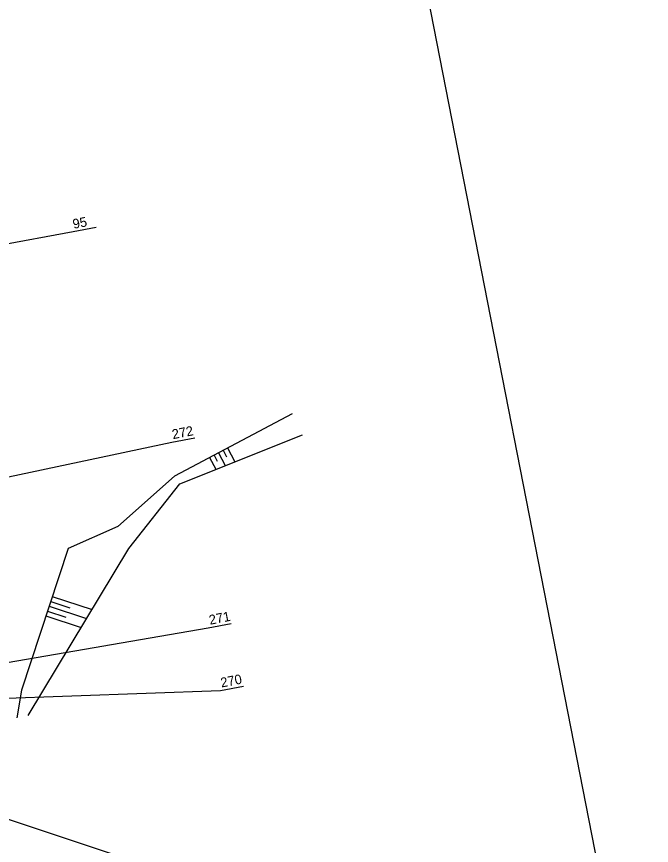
# Model space of a CAD drawing. Extents: x -545967 to -545044, y -1122650 to -1118491.
# Drawn here: x -545637.8 to -545513.8, y -1119258 to -1119096.1 of the extents above; entities that cross this region are included whole.
import ezdxf

# ---------------------------------------------------------------- set-up
doc = ezdxf.new("R2010")
doc.units = 0
for name, color, linetype in [('so180602', 7, 'Continuous'), ('Vrstva 10', 7, 'Continuous'), ('Vrstva 62', 7, 'Continuous'), ('Vrstva 63', 7, 'Continuous')]:
    doc.layers.add(name, color=color, linetype=linetype)

msp = doc.modelspace()

# ---------------------------------------------------------------- linework, layer by layer
at = {"layer": 'Vrstva 10'}
msp.add_line((-545675.17, -1118491.08), (-545513.83, -1119315.44), dxfattribs=at)
at = {"layer": 'Vrstva 62'}
for points in [[(-545584, -1119173.66), (-545606.97, -1119185.84)], [(-545615.87, -1119200), (-545605.93, -1119187.32), (-545581.98, -1119177.75)], [(-545598.35, -1119181.27), (-545597.03, -1119183.77)], [(-545597.47, -1119180.8), (-545596.78, -1119182.1)], [(-545596.59, -1119180.33), (-545595.16, -1119183.02)], [(-545600.12, -1119182.21), (-545598.9, -1119184.51)], [(-545599.24, -1119181.74), (-545598.6, -1119182.94)], [(-545606.97, -1119185.84), (-545618, -1119195.68), (-545627.74, -1119200)], [(-545627.74, -1119200), (-545636.83, -1119227.67), (-545637.76, -1119233.04)], [(-545635.55, -1119232.61), (-545615.87, -1119200)], [(-545631.13, -1119210.31), (-545627.36, -1119211.55)], [(-545630.82, -1119209.36), (-545623.06, -1119211.91)], [(-545631.75, -1119212.21), (-545628.2, -1119213.38)], [(-545631.44, -1119211.26), (-545624.12, -1119213.67)], [(-545632.07, -1119213.16), (-545625.18, -1119215.42)]]:
    msp.add_lwpolyline(points, dxfattribs=at)
at = {"layer": 'Vrstva 63'}
for p, q in [((-545622.26, -1119137.25), (-545626.71, -1119138.12)), ((-545626.71, -1119138.12), (-545690.95, -1119149.85)), ((-545607.45, -1119179.27), (-545702.19, -1119199.37)), ((-545603.01, -1119178.4), (-545607.45, -1119179.27)), ((-545603.01, -1119178.4), (-545607.45, -1119179.27)), ((-545603.01, -1119178.4), (-545607.45, -1119179.27)), ((-545600.35, -1119215.54), (-545663.35, -1119226.44)), ((-545595.91, -1119214.67), (-545600.35, -1119215.54)), ((-545595.91, -1119214.67), (-545600.35, -1119215.54)), ((-545595.91, -1119214.67), (-545600.35, -1119215.54)), ((-545597.96, -1119227.77), (-545677.04, -1119230.65)), ((-545593.51, -1119226.91), (-545597.96, -1119227.77)), ((-545593.51, -1119226.91), (-545597.96, -1119227.77)), ((-545593.51, -1119226.91), (-545597.96, -1119227.77)), ((-545589.82, -1119269.35), (-545695.29, -1119234.41))]:
    msp.add_line(p, q, dxfattribs=at)

# ---------------------------------------------------------------- texts
at = {"layer": 'so180602'}
for s, p in [('95', (-545626.64, -1119137.54)), ('272', (-545607.25, -1119178.63)), ('271', (-545600.02, -1119214.88)), ('270', (-545597.77, -1119227.14))]:
    msp.add_text(s, height=1.875, rotation=10.9955, dxfattribs=at).set_placement(p)

doc.saveas('drawing.dxf')
